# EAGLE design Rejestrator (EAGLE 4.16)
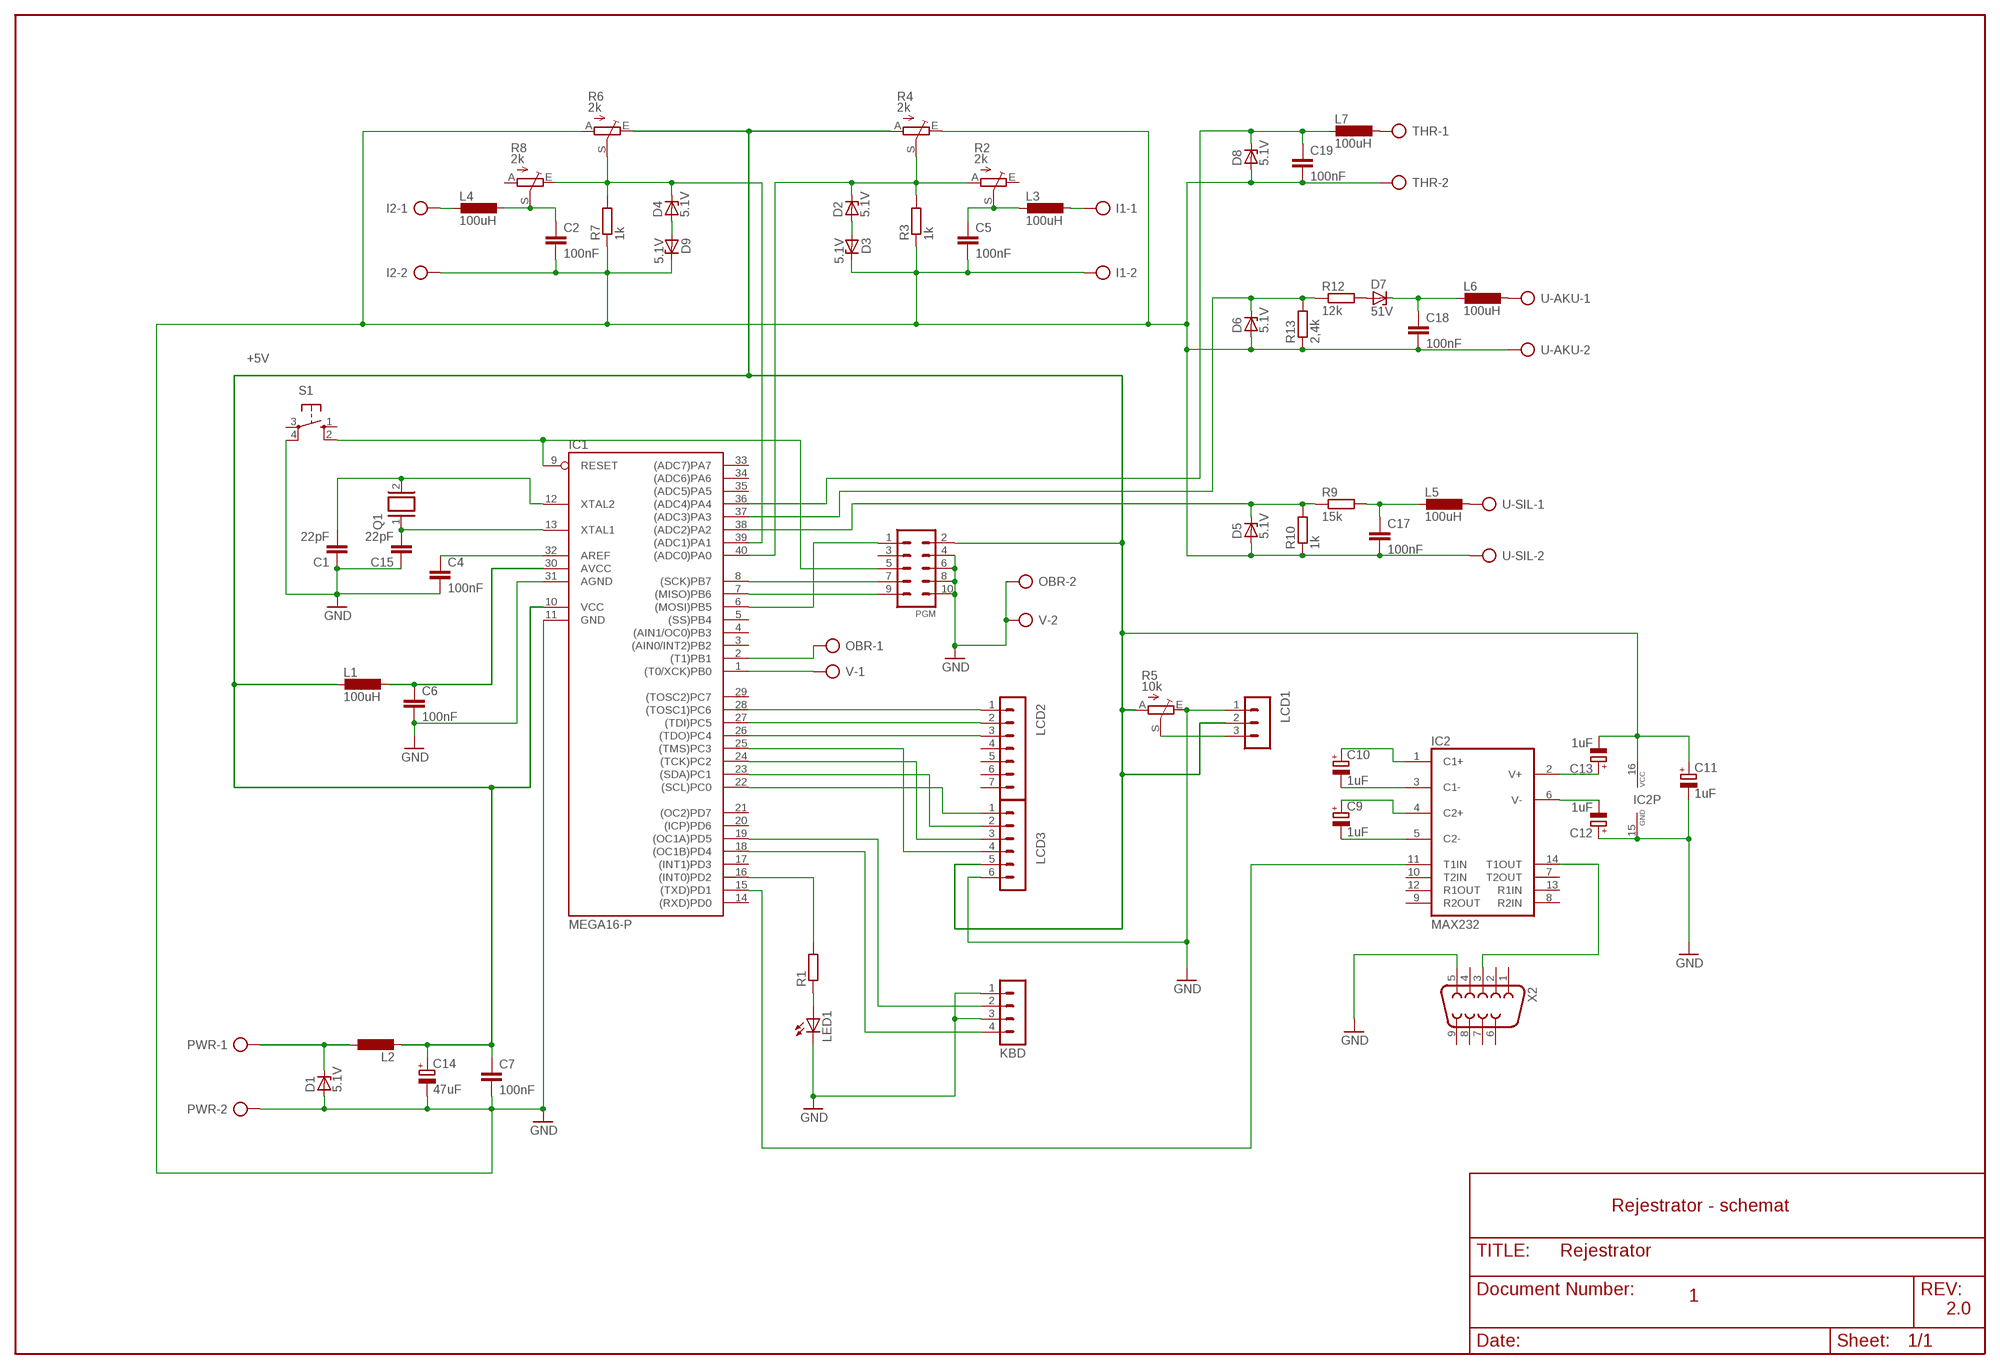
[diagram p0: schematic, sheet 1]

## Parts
C1  22pF  C-EU050-024X044  [C050-024X044]
C2  100nF  C-EU050-024X044  [C050-024X044]
C4  100nF  C-EU050-024X044  [C050-024X044]
C5  100nF  C-EU050-024X044  [C050-024X044]
C6  100nF  C-EU050-024X044  [C050-024X044]
C7  100nF  C-EU050-024X044  [C050-024X044]
C9  1uF  CPOL-EUE2.5-5  [E2,5-5]
C10  1uF  CPOL-EUE2.5-5  [E2,5-5]
C11  1uF  CPOL-EUE2.5-5  [E2,5-5]
C12  1uF  CPOL-EUE2.5-5  [E2,5-5]
C13  1uF  CPOL-EUE2.5-5  [E2,5-5]
C14  47uF  CPOL-EUE5-10.5  [E5-10,5]
C15  22pF  C-EU050-024X044  [C050-024X044]
C17  100nF  C-EU050-024X044  [C050-024X044]
C18  100nF  C-EU050-024X044  [C050-024X044]
C19  100nF  C-EU050-024X044  [C050-024X044]
D1  5.1V  ZENER-DIODEDO34-7  [DO34Z7]
D2  5.1V  ZENER-DIODEDO34-7  [DO34Z7]
D3  5.1V  ZENER-DIODEDO34-7  [DO34Z7]
D4  5.1V  ZENER-DIODEDO34-7  [DO34Z7]
D5  5.1V  ZENER-DIODEDO34-7  [DO34Z7]
D6  5.1V  ZENER-DIODEDO34-7  [DO34Z7]
D7  51V  ZENER-DIODEDO34-7  [DO34Z7]
D8  5.1V  ZENER-DIODEDO34-7  [DO34Z7]
D9  5.1V  ZENER-DIODEDO34-7  [DO34Z7]
I1  AK500/2  [AK500/2]
I2  AK500/2  [AK500/2]
IC1  MEGA16-P  [DIL40]
IC2  MAX232  [DIL16]
KBD  MA04-1  [MA04-1]
L1  100uH  L-EU0204/7  [0204/7]
L2  L-EU0207/10  [0207/10]
L3  100uH  L-EU0204/7  [0204/7]
L4  100uH  L-EU0204/7  [0204/7]
L5  100uH  L-EU0204/7  [0204/7]
L6  100uH  L-EU0204/7  [0204/7]
L7  100uH  L-EU0204/7  [0204/7]
LCD1  MA03-1  [MA03-1]
LCD2  MA07-1  [MA07-1]
LCD3  MA06-1  [MA06-1]
LED1  LED3MM  [LED3MM]
OBR  AK500/2  [AK500/2]
PGM  MA05-2  [MA05-2]
PWR  AK500/2  [AK500/2]
Q1  XTAL/S  [QS]
R1  R-EU_0204/7  [0204/7]
R2  2k  TRIM_EU-RJ9W  [RJ9W]
R3  1k  R-EU_0204/7  [0204/7]
R4  2k  TRIM_EU-RJ9W  [RJ9W]
R5  10k  TRIM_EU-B25P  [B25P]
R6  2k  TRIM_EU-RJ9W  [RJ9W]
R7  1k  R-EU_0204/7  [0204/7]
R8  2k  TRIM_EU-RJ9W  [RJ9W]
R9  15k  R-EU_0204/7  [0204/7]
R10  1k  R-EU_0204/7  [0204/7]
R12  12k  R-EU_0204/7  [0204/7]
R13  2,4k  R-EU_0204/7  [0204/7]
S1  10-XX  [B3F-10XX]
THR  AK500/2  [AK500/2]
U-AKU  AK500/2  [AK500/2]
U-SIL  AK500/2  [AK500/2]
V  AK500/2  [AK500/2]
X2  F09H  [F09H]

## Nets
+5V: C7.1 C11.+ C13.- C14.+ IC1.10(VCC) IC2.16(VCC) L1.2 L2.2 LCD1.2 LCD3.5 PGM.2 R4.A R5.A R6.E
GND: C1.1 C2.2 C4.2 C5.2 C6.2 C7.2 C11.- C12.+ C14.- C15.1 C17.2 C18.2 C19.2 D1.A D3.C D5.A D6.A D8.A D9.C I1.2 I2.2 IC1.11(GND) IC1.31(AGND) IC2.15(GND) KBD.1 KBD.3 LCD1.1 LCD3.6 LED1.K(C) OBR.2 PGM.4 PGM.6 PGM.8 PGM.10 PWR.2 R3.1 R4.E R5.E R6.A R7.1 R10.1 R13.1 S1.4(P1) THR.2 U-AKU.2 U-SIL.2 V.2 X2.5
N$1: C4.1 IC1.32(AREF)
N$2: C15.2 IC1.13(XTAL1) Q1.1
N$3: C12.- IC2.6(V-)
N$4: C1.2 IC1.12(XTAL2) Q1.2
N$5: C13.+ IC2.2(V+)
N$6: I1.1 L3.1
N$7: C9.- IC2.5(C2-)
N$8: C9.+ IC2.4(C2+)
N$9: C10.- IC2.3(C1-)
N$10: C10.+ IC2.1(C1+)
N$11: IC1.15((TXD)PD1) IC2.11(T1IN)
N$12: C5.1 L3.2 R2.S
N$13: IC2.14(T1OUT) X2.3
N$14: IC1.16((INT0)PD2) R1.2
N$15: IC1.25((TMS)PC3) LCD3.4
N$16: IC1.24((TCK)PC2) LCD3.3
N$17: IC1.23((SDA)PC1) LCD3.2
N$18: IC1.22((SCL)PC0) LCD3.1
N$19: L7.1 THR.1
N$20: D2.A D3.A
N$21: I2.1 L4.2
N$23: C6.1 IC1.30(AVCC) L1.1
N$24: IC1.18((OC1B)PD4) KBD.4
N$25: D2.C IC1.40((ADC0)PA0) R2.A R3.2 R4.S
N$26: D1.C L2.1 PWR.1
N$27: IC1.19((OC1A)PD5) KBD.2
N$28: IC1.9(RESET) PGM.5 S1.2(S1)
N$29: L5.1 U-SIL.1
N$30: D7.A R12.2
N$31: D5.C IC1.38((ADC2)PA2) R9.1 R10.2
N$32: C17.1 L5.2 R9.2
N$33: L6.1 U-AKU.1
N$34: D6.C IC1.37((ADC3)PA3) R12.1 R13.2
N$35: C18.1 D7.C L6.2
N$36: IC1.2((T1)PB1) OBR.1
N$37: IC1.1((T0/XCK)PB0) V.1
N$38: C19.1 D8.C IC1.36((ADC4)PA4) L7.2
N$39: IC1.6((MOSI)PB5) PGM.1
N$40: IC1.8((SCK)PB7) PGM.7
N$41: IC1.7((MISO)PB6) PGM.9
N$42: C2.1 L4.1 R8.S
N$43: IC1.28((TOSC1)PC6) LCD2.1
N$44: D4.A D9.A
N$45: D4.C IC1.39((ADC1)PA1) R6.S R7.2 R8.E
N$48: IC1.26((TDO)PC4) LCD2.3
N$49: IC1.27((TDI)PC5) LCD2.2
N$50: LED1.A R1.1
N$51: LCD1.3 R5.S
Unconnected: IC1.3((AIN0/INT2)PB2) IC1.4((AIN1/OC0)PB3) IC1.5((SS)PB4) IC1.14((RXD)PD0) IC1.17((INT1)PD3) IC1.20((ICP)PD6) IC1.21((OC2)PD7) IC1.29((TOSC2)PC7) IC1.33((ADC7)PA7) IC1.34((ADC6)PA6) IC1.35((ADC5)PA5) IC2.7(T2OUT) IC2.8(R2IN) IC2.9(R2OUT) IC2.10(T2IN) IC2.12(R1OUT) IC2.13(R1IN) LCD2.4 LCD2.5 LCD2.6 LCD2.7 PGM.3 R2.E R8.A S1.1(S) S1.3(P) X2.1 X2.2 X2.4 X2.6 X2.7 X2.8 X2.9

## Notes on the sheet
- Rejestrator - schemat
- 1
- 2.0

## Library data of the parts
C1 C2 C4-C7 C15 C17-C19 = rcl:C-EU: CAPACITOR, European symbol
C9-C14 = rcl:CPOL-EU: POLARIZED CAPACITOR, European symbol
D1-D9 = diode:ZENER-DIODE: Z-Diode
I1 I2 OBR PWR THR U-AKU U-SIL V = con-ptr500:AK500/2: CONNECTOR
IC1 = atmel:MEGA16-P: MICROCONTROLLER 16 Kbytes FLASH 1 kbytes SRAM 512 bytes EEPROM USART 8-channel 10 bit ADC Source: avr.lbr
IC2 = maxim:MAX232: RS232 TRANSEIVER
KBD = con-lstb:MA04-1: PIN HEADER
L1-L7 = rcl:L-EU: INDUCTOR, European symbol
LCD1 = con-lstb:MA03-1: PIN HEADER
LCD2 = con-lstb:MA07-1: PIN HEADER
LCD3 = con-lstb:MA06-1: PIN HEADER
LED1 = led:LED: LED
PGM = con-lstb:MA05-2: PIN HEADER
Q1 = special:XTAL/S: CRYSTAL
R1 R3 R7 R9 R10 R12 R13 = rcl:R-EU_: RESISTOR, European symbol
R2 R4-R6 R8 = pot:TRIM_EU-: POTENTIOMETER
S1 = switch-omron:10-XX: OMRON SWITCH
X2 = con-subd:F09: SUB-D

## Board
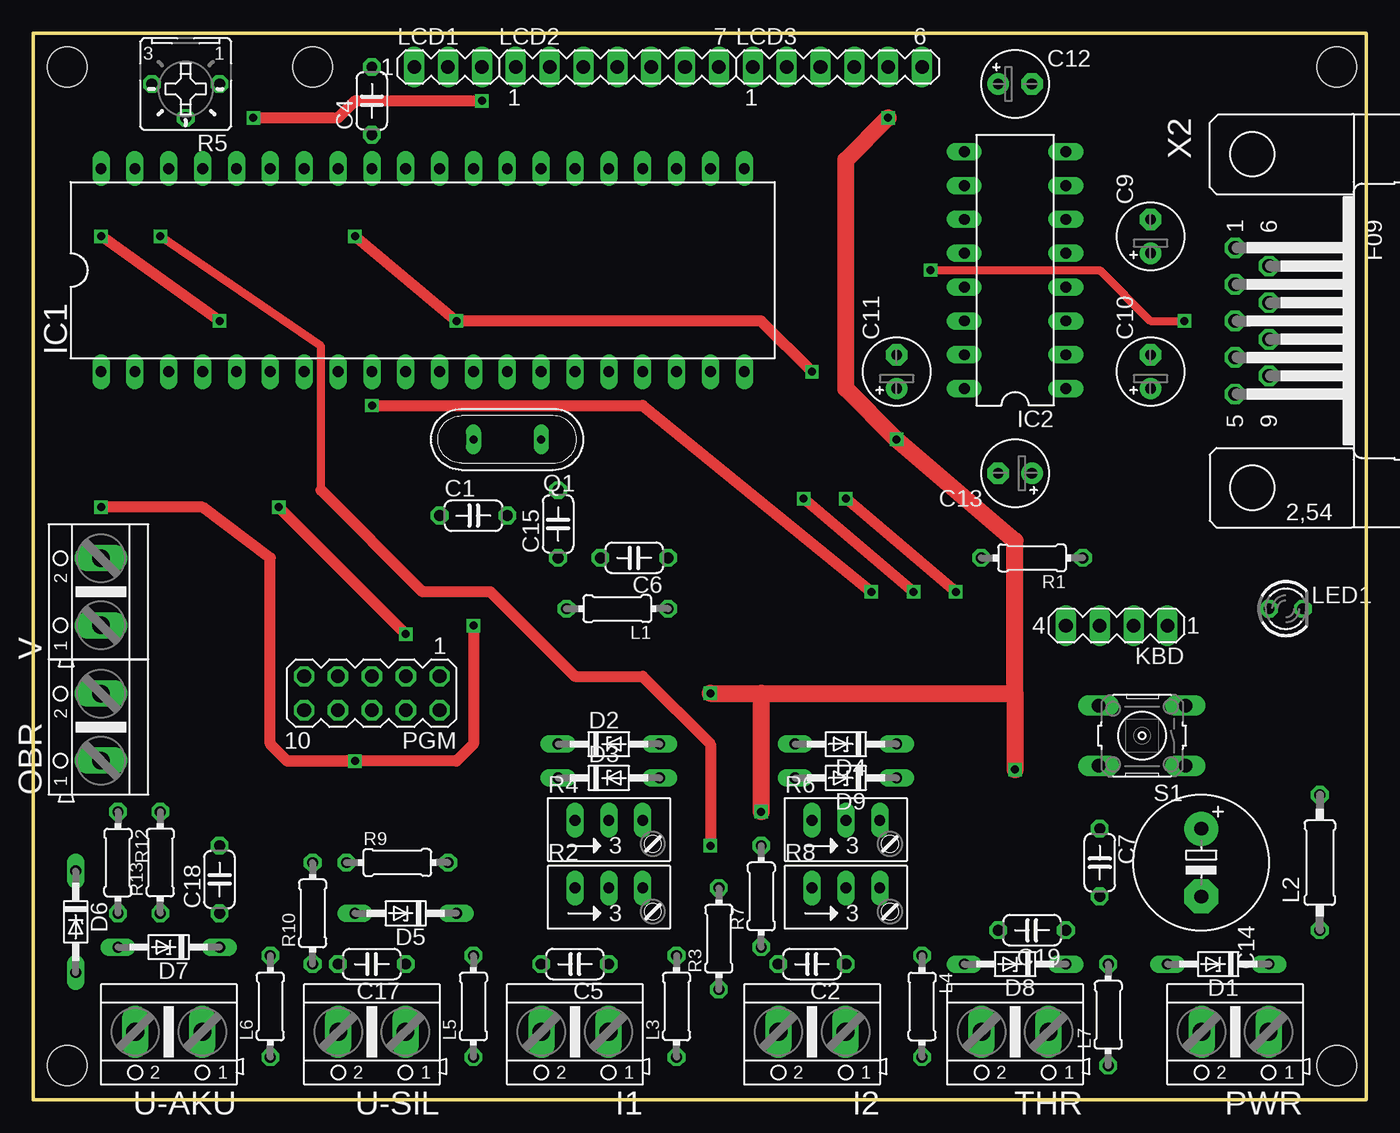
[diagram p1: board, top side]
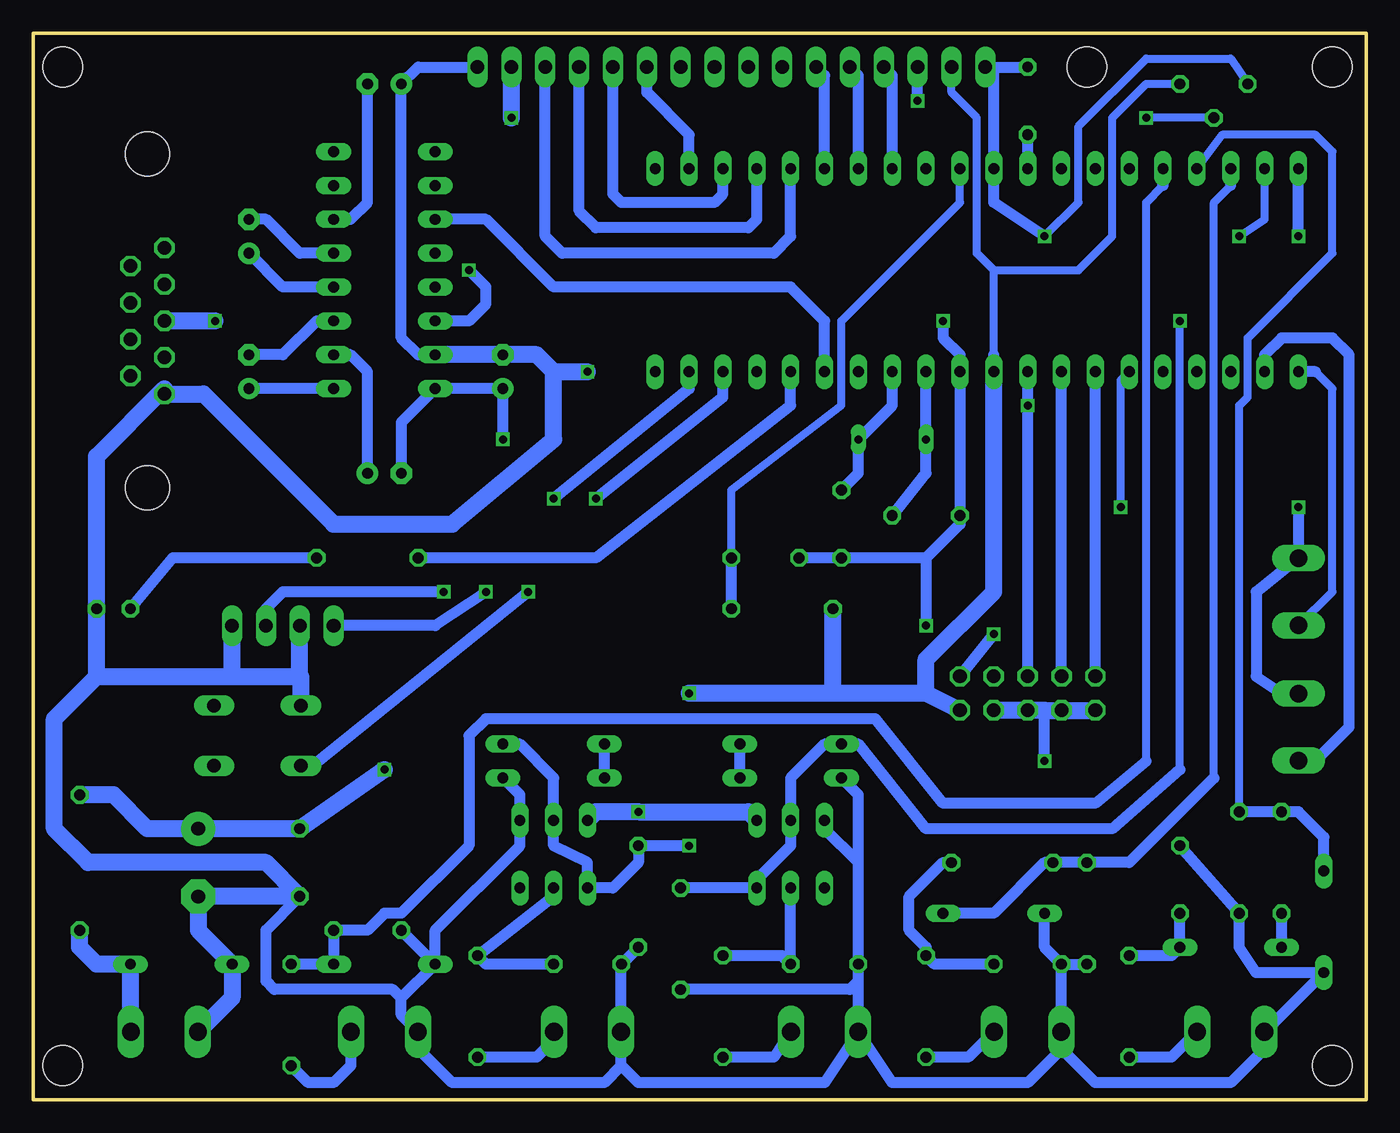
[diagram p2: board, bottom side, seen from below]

Size 100 x 80 mm. Coordinates in mm from the lower left corner, seen from the top.
Outline: 0,0 100,0 100,80 0,80 0,0
Copper layers (1*16): Top 0.035mm / dielectric 1.5mm / Bottom 0.035mm
Design rules "default": minimum track width 10mil, minimum drill 24mil, track to track 8mil, track to pad 8mil, pad to pad 8mil, via to via 8mil, smd to smd 8mil, copper to edge 40mil, drill to drill 8mil, minimum pad ring 10mil, minimum via ring 8mil, stop-mask expansion 4mil, vias tented up to drill 0mil, thermal gap 10mil
Holes 3 mm at 2.54,77.47 97.79,77.47 97.79,2.54 2.54,2.54 20.95,77.47

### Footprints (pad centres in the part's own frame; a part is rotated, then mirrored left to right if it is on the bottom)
C050-024X044 = drill 0.813 octagon: 1 -2.54,0; 2 2.54,0
E2,5-5 = drill 0.813 pad 1.6 round: + -1.27,0 | drill 0.813 pad 1.6 octagon: - 1.27,0
E5-10,5 = drill 1.016 pad 2.54 round: + -2.54,0 | drill 1.016 pad 2.54 octagon: - 2.54,0
DO34Z7 = drill 0.813 long: A 3.81,0; C -3.81,0
AK500/2 = drill 1.321 long: 1 -2.515,0; 2 2.515,0
DIL40 = drill 0.813 long: 1 -24.13,-7.62; 2 -21.59,-7.62; 3 -19.05,-7.62; 4 -16.51,-7.62; 5 -13.97,-7.62; 6 -11.43,-7.62; 7 -8.89,-7.62; 8 -6.35,-7.62; 9 -3.81,-7.62; 10 -1.27,-7.62; 11 1.27,-7.62; 12 3.81,-7.62; 13 6.35,-7.62; 14 8.89,-7.62; 15 11.43,-7.62; 16 13.97,-7.62; 17 16.51,-7.62; 18 19.05,-7.62; 19 21.59,-7.62; 20 24.13,-7.62; 21 24.13,7.62; 22 21.59,7.62; 23 19.05,7.62; 24 16.51,7.62; 25 13.97,7.62; 26 11.43,7.62; 27 8.89,7.62; 28 6.35,7.62; 29 3.81,7.62; 30 1.27,7.62; 31 -1.27,7.62; 32 -3.81,7.62; 33 -6.35,7.62; 34 -8.89,7.62; 35 -11.43,7.62; 36 -13.97,7.62; 37 -16.51,7.62; 38 -19.05,7.62; 39 -21.59,7.62; 40 -24.13,7.62
DIL16 = drill 0.813 long: 1 -8.89,-3.81; 2 -6.35,-3.81; 3 -3.81,-3.81; 4 -1.27,-3.81; 5 1.27,-3.81; 6 3.81,-3.81; 7 6.35,-3.81; 8 8.89,-3.81; 9 8.89,3.81; 10 6.35,3.81; 11 3.81,3.81; 12 1.27,3.81; 13 -1.27,3.81; 14 -3.81,3.81; 15 -6.35,3.81; 16 -8.89,3.81
MA04-1 = drill 1.016 long: 1 -3.81,0; 2 -1.27,0; 3 1.27,0; 4 3.81,0
0204/7 = drill 0.813 octagon: 1 -3.81,0; 2 3.81,0
0207/10 = drill 0.813 octagon: 1 -5.08,0; 2 5.08,0
MA03-1 = drill 1.016 long: 1 -2.54,0; 2 0,0; 3 2.54,0
MA07-1 = drill 1.016 long: 1 -7.62,0; 2 -5.08,0; 3 -2.54,0; 4 0,0; 5 2.54,0; 6 5.08,0; 7 7.62,0
MA06-1 = drill 1.016 long: 1 -6.35,0; 2 -3.81,0; 3 -1.27,0; 4 1.27,0; 5 3.81,0; 6 6.35,0
LED3MM = drill 0.813 octagon: A -1.27,0; K 1.27,0
MA05-2 = drill 1.016 octagon: 1 -5.08,-1.27; 2 -5.08,1.27; 3 -2.54,-1.27; 4 -2.54,1.27; 5 0,-1.27; 6 0,1.27; 7 2.54,-1.27; 8 2.54,1.27; 9 5.08,-1.27; 10 5.08,1.27
QS = drill 0.61 long: 1 -2.54,0; 2 2.54,0
RJ9W = drill 0.813 long: A 2.54,0.635; E -2.54,0.635; S 0,0.635
B25P = drill 0.813 octagon: A -2.54,0; E 2.54,0; S 0,2.54
B3F-10XX = drill 1.016 long: 1 -3.251,2.261; 2 3.251,2.261; 3 -3.251,-2.261; 4 3.251,-2.261
F09H = drill 1.016 octagon: 1 -5.486,-1.27; 2 -2.743,-1.27; 3 0,-1.27; 4 2.743,-1.27; 5 5.486,-1.27; 6 -4.115,1.27; 7 -1.372,1.27; 8 1.372,1.27; 9 4.115,1.27 | hole 3.302: -12.522,0; 12.522,0

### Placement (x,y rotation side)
C1  33.02,43.81 0 top
C2  58.42,10.16 180 top
C4  25.4,74.93 90 top
C5  40.64,10.16 180 top
C6  45.09,40.64 180 top
C7  80.01,17.78 270 top
C9  83.82,64.77 90 top
C10  83.82,54.61 90 top
C11  64.77,54.61 90 top
C12  73.66,76.2 0 top
C13  73.66,46.99 180 top
C14  87.63,17.78 270 top
C15  39.37,43.18 90 top
C17  25.4,10.16 180 top
C18  13.97,16.51 90 top
C19  74.93,12.7 180 top
D1  88.9,10.16 180 top
D2  43.18,26.67 0 top
D3  43.18,24.13 0 top
D4  60.96,26.67 180 top
D5  27.94,13.97 180 top
D6  3.17,13.34 270 top
D7  10.16,11.43 180 top
D8  73.66,10.16 180 top
D9  60.96,24.13 180 top
I1  40.64,5.08 180 top
I2  58.42,5.08 180 top
IC1  29.21,62.23 0 top
IC2  73.66,62.23 90 top
KBD  81.28,35.56 180 top
L1  43.81,36.83 180 top
L2  96.52,17.78 90 top
L3  48.26,6.99 90 top
L4  66.67,6.99 270 top
L5  33.02,6.99 90 top
L6  17.78,6.99 90 top
L7  80.64,6.35 90 top
LCD1  31.11,77.47 0 top
LCD2  43.81,77.47 0 top
LCD3  60.33,77.47 0 top
LED1  93.98,36.83 0 top
OBR  5.08,27.94 90 top
PGM  25.4,30.48 180 top
PWR  90.17,5.08 180 top
Q1  35.56,49.53 180 top
R1  74.93,40.64 180 top
R2  43.18,15.24 0 top
R3  51.44,12.06 90 top
R4  43.18,20.32 0 top
R5  11.43,76.2 180 top
R6  60.96,20.32 0 top
R7  54.61,15.24 90 top
R8  60.96,15.24 0 top
R9  27.3,17.78 0 top
R10  20.95,13.97 90 top
R12  6.35,17.78 270 top
R13  9.53,17.78 90 top
S1  83.19,27.3 180 top
THR  73.66,5.08 180 top
U-AKU  10.16,5.08 180 top
U-SIL  25.4,5.08 180 top
V  5.08,38.1 90 top
X2  91.44,58.42 270 top

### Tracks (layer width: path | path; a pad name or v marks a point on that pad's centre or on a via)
+5V  (via drill 0.6)
  Top 1.27: 73.66,30.48 v73.66,24.77 | 54.61,30.48 73.66,30.48 | 54.61,30.48 v54.61,21.59 | 73.66,30.48 73.66,41.91 v64.77,49.53 60.96,53.34 60.96,70.48 v64.14,73.66 | v50.8,30.48 54.61,30.48
  Bottom 0.61: LCD1.2 31.11,75.56 29.21,73.66 29.21,63.5 27.94,62.23 | 27.94,55.88 27.94,62.23 | R5.A 16.51,76.2 19.05,73.66 19.05,64.77 21.59,62.23 27.94,62.23
  Bottom 0.813: C13.- 72.39,50.8 IC2.16 C11.+ v64.77,49.53 | IC1.10 27.94,55.88
  Bottom 1.27: L2.2 93.98,22.86 91.44,20.32 C14.+ C7.1 v73.66,24.77 | PGM.2 33.02,30.48 | 33.02,30.48 33.02,33.02 27.94,38.1 IC1.10 | R4.A 46.35,21.59 v54.61,21.59 57.78,21.59 R6.E | 40.01,30.48 v50.8,30.48 | 40.01,30.48 L1.2 | 33.02,30.48 40.01,30.48 | v64.14,73.66 LCD3.5
GND  (via drill 0.6)
  Top 0.813: v24.13,64.77 v31.75,58.42 54.61,58.42 v58.42,54.61 | 19.05,25.4 v24.13,25.4 | 19.05,25.4 17.78,26.67 17.78,40.64 12.7,44.45 v5.08,44.45 | 19.05,25.4 31.75,25.4 33.02,26.67 v33.02,35.56
  Bottom 0.61: R5.E 10.16,78.11 16.51,78.11 21.59,73.03 21.59,67.31 v24.13,64.77
  Bottom 0.813: 87.63,5.08 PWR.2 | 72.39,7.62 73.03,8.26 81.92,8.26 82.55,8.89 82.55,12.7 C7.2 | 72.39,7.62 72.39,6.35 71.12,5.08 | IC2.15 71.12,55.88 72.39,57.15 C12.+ 71.12,77.47 LCD3.6 | 33.02,40.64 30.48,43.18 C1.1 IC1.11 30.48,55.88 31.75,57.15 v31.75,58.42 | D8.A C19.2 | 55.91,2.54 55.91,2.52 57.15,1.27 68.58,1.27 71.12,3.81 71.12,5.08 | 55.91,2.54 I2.2 55.91,10.13 C2.2 | 71.12,5.08 THR.2 | C2.2 R7.1 C2.2 | 72.39,7.62 D8.A | D9.C 63.5,22.86 R6.A 63.5,19.05 69.85,12.7 D8.A | 38.1,5.08 38.12,5.11 | 38.1,5.08 40.64,1.27 54.61,1.27 55.88,2.54 55.91,2.54 | 22.89,3.81 22.89,3.79 25.4,1.27 35.56,1.27 38.1,5.08 | 22.89,3.81 U-SIL.2 22.89,10.13 C17.2 | C17.2 24.13,11.43 D5.A | C17.2 R10.1 | 22.89,3.81 22.86,3.81 20.32,1.27 10.16,1.27 7.62,3.81 7.64,3.83 U-AKU.2 7.62,5.08 D6.A 8.26,9.53 9.53,11.43 R13.1 C18.2 | R4.E 40.64,20.32 38.1,17.78 38.1,5.08 | 27.94,77.47 C4.2 | 27.94,77.47 LCD1.1 | 27.94,77.47 IC1.31 27.94,67.31 v24.13,64.77 | C6.2 C15.1 33.02,40.64 | OBR.2 5.08,30.48 6.35,30.48 8.26,31.75 8.26,38.1 5.11,40.62 V.2 v5.08,44.45 | PGM.10 24.13,29.21 v24.13,25.4 | 33.02,40.64 v33.02,35.56 | 38.1,5.08 I1.2 | 38.73,8.26 R3.1 | 38.1,5.08 38.1,8.26 38.73,8.26 | 38.73,8.26 38.1,8.89 C5.2 38.1,22.86 D3.C
  Bottom 1.016: 90.17,53.34 X2.5
  Bottom 1.27: 87.63,5.08 85.09,7.62 D1.A 87.63,12.7 C14.- C7.2 82.55,17.78 95.89,17.78 98.42,20.32 98.42,28.57 95.25,31.75 | IC2.15 C11.- 62.23,55.88 60.96,54.61 | 95.25,31.75 LED1.K 95.25,48.26 90.17,53.34 | X2.5 87.22,52.93 77.47,43.18 68.58,43.18 60.96,49.53 60.96,54.61 | S1.4 79.93,31.67 80.01,31.75 | 85.09,31.75 KBD.1 | 80.01,31.75 KBD.3 | 85.09,31.75 80.01,31.75 | 95.25,31.75 85.09,31.75 | PGM.10 PGM.8 24.13,29.21 PGM.6 PGM.4 | 60.96,54.61 v58.42,54.61
N$1
  Bottom 0.813: IC1.32 C4.1
N$2
  Bottom 0.813: IC1.13 35.56,52.07 Q1.1 38.1,46.99 C15.2
N$3
  Bottom 0.813: C12.- 74.93,67.31 76.2,66.04 IC2.6
N$4
  Bottom 0.813: IC1.12 Q1.2 33.02,46.99 C1.2
N$5
  Bottom 0.813: C13.+ 74.93,54.61 76.2,55.88 IC2.2
N$6
  Bottom 0.813: I1.1 43.16,5.11 44.45,3.17 L3.1
N$7
  Bottom 0.813: IC2.5 80.01,63.5 82.55,66.04 C9.-
N$8
  Bottom 0.813: IC2.4 81.28,60.96 C9.+
N$9
  Bottom 0.813: C10.- 81.28,55.88 78.74,58.42 IC2.3
N$10
  Bottom 0.813: IC2.1 C10.+
N$11
  Bottom 0.813: IC1.15 40.64,58.42 43.18,60.96 60.96,60.96 66.04,66.04 IC2.11
N$12
  Bottom 0.813: L3.2 43.81,10.79 C5.1 R2.S 43.18,16.51
N$13  (via drill 0.6)
  Top 0.61: v67.31,62.23 80.01,62.23 83.82,58.42 v86.36,58.42
  Bottom 0.813: IC2.14 67.31,58.42 66.04,59.69 66.04,60.96 v67.31,62.23
  Bottom 1.27: v86.36,58.42 X2.3
N$14
  Bottom 0.813: IC1.16 43.18,52.07 57.78,40.64 R1.2
N$15
  Bottom 0.813: IC1.25 43.18,64.77 44.45,63.5 60.33,63.5 61.59,64.77 LCD3.4
N$16
  Bottom 0.813: IC1.24 45.72,66.04 46.35,65.41 57.78,65.41 59.05,66.67 LCD3.3
N$17
  Bottom 0.813: IC1.23 48.26,67.94 48.9,67.31 55.88,67.31 56.52,67.94 LCD3.2
N$18
  Bottom 0.813: IC1.22 50.8,72.39 53.98,75.56 LCD3.1
N$19
  Bottom 0.813: THR.1 76.17,2.56 77.47,1.27 79.38,1.27 L7.1
N$20
  Bottom 0.813: D3.A D2.A
N$21
  Bottom 0.813: 60.94,5.11 I2.1 60.94,4.47 62.23,3.17 L4.2
N$23
  Bottom 0.61: C6.1 47.62,45.72 39.37,52.07 39.37,58.42 30.48,67.31 IC1.30
  Bottom 0.813: L1.1 C6.1
N$24  (via drill 0.6)
  Top 0.813: v57.78,45.09 v66.04,38.1
  Bottom 0.813: KBD.4 69.85,35.56 v66.04,38.1 | v57.78,45.09 48.26,52.7 IC1.18
N$25  (via drill 0.6)
  Top 0.813: v13.97,58.42 v5.08,64.77
  Bottom 0.61: 13.97,24.77 v13.97,58.42
  Bottom 0.813: R3.2 R2.A 45.72,16.51 43.18,19.05 R4.S 43.18,24.13 40.64,26.67 D2.C 38.1,26.67 33.02,20.32 19.05,20.32 13.97,24.77 | v5.08,64.77 IC1.40
N$26
  Bottom 0.813: PWR.1 92.71,5.08
  Bottom 1.27: 92.71,5.08 D1.C 95.25,10.16 96.52,11.43 L2.1
N$27  (via drill 0.6)
  Top 0.813: v60.96,45.09 v69.22,38.1
  Bottom 0.813: KBD.2 82.55,36.83 81.28,38.1 v69.22,38.1 | v60.96,45.09 50.8,53.34 IC1.19
N$28  (via drill 0.6)
  Top 0.813: v62.87,38.1 45.72,52.07 v25.4,52.07
  Bottom 0.813: PGM.5 v25.4,52.07 IC1.9 | S1.2 79.73,25.04 79.38,24.77 v62.87,38.1
N$29
  Bottom 0.813: U-SIL.1 27.94,5.08 29.84,3.17 L5.1
N$30
  Bottom 0.813: D7.A R12.2
N$31
  Bottom 0.61: 11.43,24.13 11.43,67.31 10.16,68.58
  Bottom 0.813: D5.C 27.94,13.97 24.13,17.78 R9.1 R10.2 17.78,17.78 11.43,24.13 | 10.16,68.58 IC1.38
N$32
  Bottom 0.813: C17.1 32.38,10.16 L5.2 33.02,11.43 34.29,12.7 34.29,15.24 31.75,17.78 R9.2
N$33
  Bottom 0.813: U-AKU.1 12.7,5.08 14.61,3.17 L6.1
N$34
  Bottom 0.61: R13.2 9.53,52.07 8.89,52.7 8.89,57.15 2.54,63.5 2.54,71.12 3.81,72.39 10.79,72.39 IC1.37
  Bottom 0.813: D6.C 3.17,19.68 5.08,21.59 R12.1 R13.2
N$35
  Bottom 0.813: L6.2 14.61,10.79 D7.C C18.1
N$36
  Bottom 0.813: OBR.1 3.79,25.43 1.27,27.94 1.27,55.88 2.54,57.15 6.35,57.15 7.62,55.88 IC1.2
N$37
  Bottom 0.61: 3.81,54.61 2.54,53.34 2.54,38.1 5.08,35.56
  Bottom 0.813: 3.81,54.61 IC1.1 | V.1 5.08,35.56
N$38
  Bottom 0.61: 16.51,25.4 16.51,67.31 15.24,68.58
  Bottom 0.813: L7.2 D8.C C19.1 74.93,12.7 73.66,13.97 72.39,13.97 67.31,19.05 67.31,27.3 66.04,28.57 36.83,28.57 31.75,22.23 20.32,22.23 16.51,25.4 | 15.24,68.58 IC1.36
N$39  (via drill 0.6)
  Top 0.813: v27.94,34.92 v18.41,44.45
  Bottom 0.61: v18.41,44.45 18.41,53.98 IC1.6
  Bottom 0.813: PGM.1 v27.94,34.92
N$40
  Bottom 0.813: PGM.7 IC1.8
N$41
  Bottom 0.813: PGM.9 IC1.7
N$42
  Bottom 0.813: C2.1 66.04,10.16 L4.1 60.96,15.24 R8.S
N$43
  Bottom 0.813: IC1.28 35.56,76.83 LCD2.1
N$44
  Bottom 0.813: D9.A D4.A
N$45  (via drill 0.6)
  Top 0.61: v9.53,64.77 21.59,56.52 21.59,45.72
  Top 0.813: 21.59,45.72 29.21,38.1 34.29,38.1 40.64,31.75 45.72,31.75 50.8,26.67 v50.8,19.05
  Bottom 0.61: v9.53,64.77 7.62,66.04 IC1.39
  Bottom 0.813: D4.C 63.5,26.67 60.96,24.13 R6.S 60.96,19.05 58.42,17.78 R8.E 56.52,15.88 54.61,17.78 R7.2 v50.8,19.05
N$48
  Bottom 0.813: IC1.26 40.64,76.83 LCD2.3
N$49
  Bottom 0.813: IC1.27 38.1,76.83 LCD2.2
N$50
  Bottom 0.813: R1.1 89.53,40.64 LED1.A
N$51  (via drill 0.6)
  Top 0.813: v16.51,73.66 22.86,73.66 24.13,74.93 v33.66,74.93
  Bottom 0.61: R5.S v16.51,73.66
  Bottom 0.813: v33.66,74.93 LCD1.3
